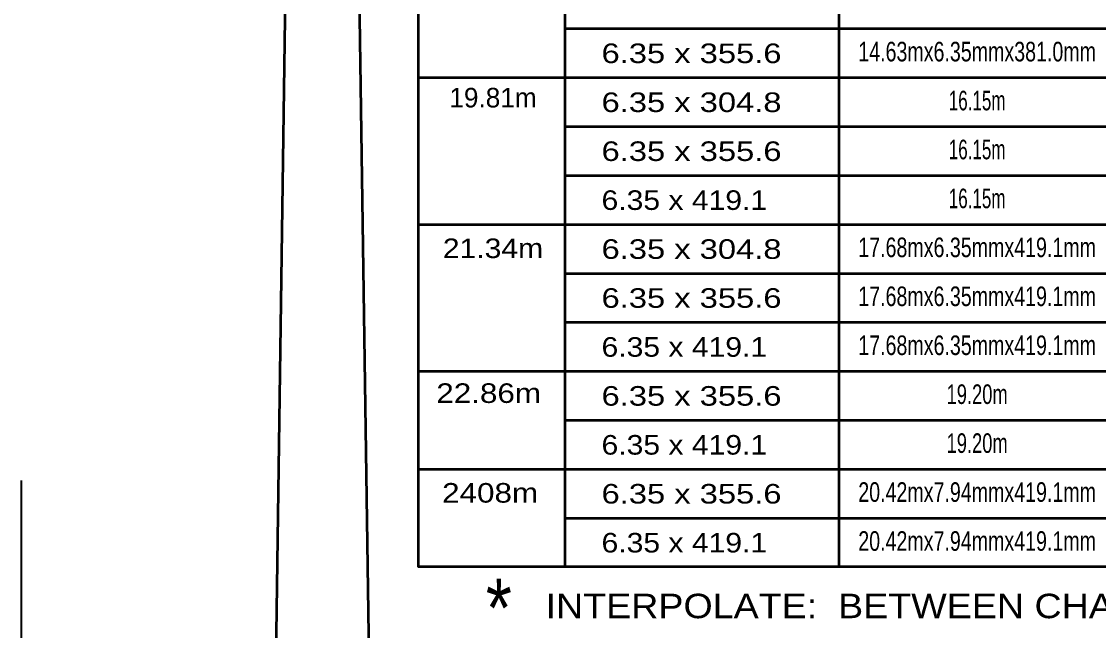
# Model space of a CAD drawing. Extents: x -34 to 822, y -23 to 521.
# Drawn here: x 528.6 to 660.8, y 287.6 to 362.2 of the extents above; entities that cross this region are included whole.
import ezdxf
from ezdxf.enums import TextEntityAlignment as Align

# ---------------------------------------------------------------- set-up
doc = ezdxf.new("R2010")
doc.units = 0
doc.header["$LTSCALE"] = 1.2
doc.layers.add('1', color=7, linetype='Continuous', lineweight=35)

msp = doc.modelspace()

# ---------------------------------------------------------------- linework, layer by layer
at = {"layer": '1', "lineweight": 53}
for p, q in [((595.354, 295.349), (595.354, 470.549)), ((628.954, 295.349), (628.954, 470.549)), ((561.663, 411.49), (559.59, 265.442)), ((569.431, 411.529), (571.505, 265.442)), ((595.354, 361.349), (796.954, 361.349)), ((577.354, 355.349), (796.954, 355.349)), ((595.354, 349.349), (796.954, 349.349)), ((595.354, 343.349), (796.954, 343.349)), ((577.354, 337.349), (796.954, 337.349)), ((595.354, 331.349), (796.954, 331.349)), ((595.354, 325.349), (796.954, 325.349)), ((577.354, 319.349), (796.954, 319.349)), ((595.354, 313.349), (796.954, 313.349)), ((577.354, 307.349), (796.954, 307.349)), ((595.354, 301.349), (796.954, 301.349))]:
    msp.add_line(p, q, dxfattribs=at)
at = {"layer": '1'}
msp.add_line((528.648, 253.142), (528.648, 305.942), dxfattribs=at)
at = {"layer": '1', "lineweight": 53}
msp.add_lwpolyline([(577.354, 482.549), (796.954, 482.549), (796.954, 295.349), (577.354, 295.349)], close=True, dxfattribs=at)

# ---------------------------------------------------------------- texts
at = {"layer": '1'}
for s, height, width, p in [('6.35 x 355.6', 2.4, 1.25, (599.804, 357.126)), ('6.35 x 304.8', 2.4, 1.25, (599.804, 351.126)), ('6.35 x 355.6', 2.4, 1.25, (599.804, 345.126)), ('6.35 x 419.1', 2.4, 1.15, (599.804, 339.126)), ('6.35 x 304.8', 2.4, 1.25, (599.804, 333.126)), ('6.35 x 355.6', 2.4, 1.25, (599.804, 327.126)), ('6.35 x 419.1', 2.4, 1.15, (599.804, 321.126)), ('6.35 x 355.6', 2.4, 1.25, (599.804, 315.126)), ('6.35 x 419.1', 2.4, 1.15, (599.804, 309.126)), ('6.35 x 355.6', 2.4, 1.25, (599.804, 303.126)), ('6.35 x 419.1', 2.4, 1.15, (599.804, 297.126)), ('INTERPOLATE:  BETWEEN CHARTED VALUES FOR GAP OR UNSYMMETRICAL LOADING', 3, 1.15, (592.936, 289.07))]:
    msp.add_text(s, height=height, dxfattribs=dict(at, width=width)).set_placement(p)
for s, height, width, p in [('14.63mx6.35mmx381.0mm', 2.4, 0.75, (645.884, 357.335)), ('16.15m', 2.4, 0.65, (645.884, 351.335)), ('16.15m', 2.4, 0.65, (645.884, 345.335)), ('16.15m', 2.4, 0.65, (645.884, 339.335)), ('21.34m', 2.4, 1.15, (586.488, 333.222)), ('17.68mx6.35mmx419.1mm', 2.4, 0.75, (645.884, 333.335)), ('17.68mx6.35mmx419.1mm', 2.4, 0.75, (645.884, 327.335)), ('17.68mx6.35mmx419.1mm', 2.4, 0.75, (645.884, 321.335)), ('22.86m', 2.4, 1.2, (585.955, 315.462)), ('19.20m', 2.4, 0.7, (645.884, 315.335)), ('19.20m', 2.4, 0.7, (645.884, 309.335)), ('2408m', 2.4, 1.2, (586.134, 303.239)), ('20.42mx7.94mmx419.1mm', 2.4, 0.75, (645.884, 303.335)), ('20.42mx7.94mmx419.1mm', 2.4, 0.75, (645.884, 297.335)), ('*', 7.2, 0.85, (587.205, 286.726))]:
    msp.add_text(s, height=height, dxfattribs=dict(at, width=width)).set_placement(p, align=Align.CENTER)
msp.add_text('19.81m', height=2.4, dxfattribs=at).set_placement((586.488, 351.692), align=Align.CENTER)

doc.saveas('drawing.dxf')
